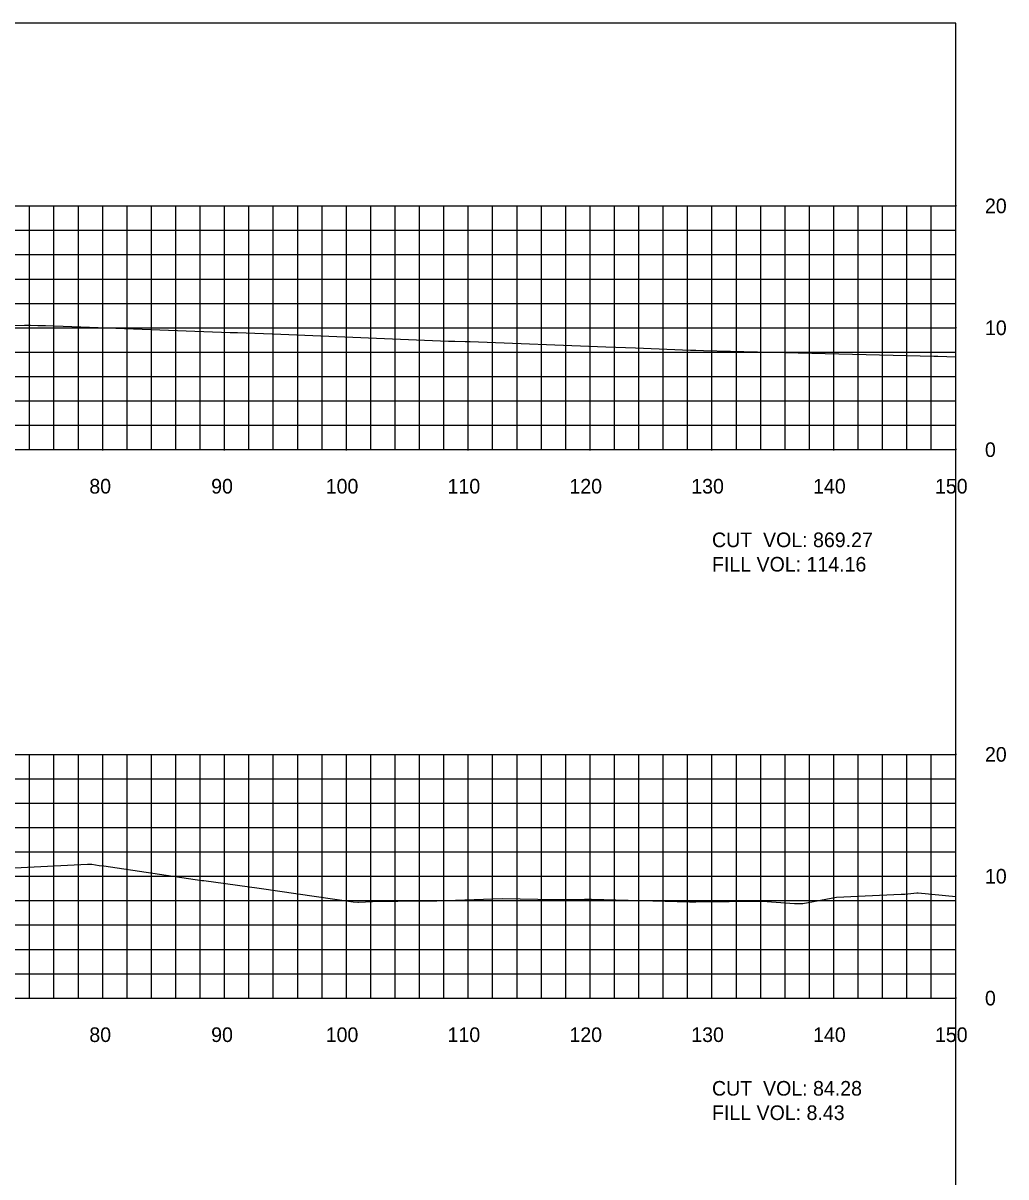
# Model space of a CAD drawing. Extents: x 1797419 to 1809236, y 248759 to 251512.
# Drawn here: x 1804404.5 to 1804485.1, y 250174.8 to 250269.4 of the extents above; entities that cross this region are included whole.
import ezdxf

# ---------------------------------------------------------------- set-up
doc = ezdxf.new("R2010")
doc.units = 0
for name, color, linetype in [('10', 7, 'Continuous'), ('31', 7, 'Continuous'), ('60', 7, 'Continuous'), ('ANNO-TXT', 7, 'Continuous'), ('Level 62', 7, 'Continuous'), ('M-ROADS', 7, 'Continuous')]:
    doc.layers.add(name, color=color, linetype=linetype)

msp = doc.modelspace()

# ---------------------------------------------------------------- linework, layer by layer
msp.add_lwpolyline([(1804181.002, 250079.432), (1804481.002, 250079.432), (1804481.002, 250269.432), (1804181.002, 250269.432)], close=True)
at = {"layer": '60'}
for p, q in [((1804481.002, 250234.432), (1804481.002, 250254.432)), ((1804481.062, 250254.432), (1804481.002, 250254.432)), ((1804481.062, 250244.432), (1804481.002, 250244.432)), ((1804181.002, 250234.432), (1804481.002, 250234.432)), ((1804411.002, 250234.372), (1804411.002, 250234.432)), ((1804421.002, 250234.372), (1804421.002, 250234.432)), ((1804431.002, 250234.372), (1804431.002, 250234.432)), ((1804441.002, 250234.372), (1804441.002, 250234.432)), ((1804451.002, 250234.372), (1804451.002, 250234.432)), ((1804461.002, 250234.372), (1804461.002, 250234.432)), ((1804471.002, 250234.372), (1804471.002, 250234.432)), ((1804481.002, 250234.372), (1804481.002, 250234.432)), ((1804481.062, 250234.432), (1804481.002, 250234.432)), ((1804481.002, 250189.432), (1804481.002, 250209.432)), ((1804481.062, 250209.432), (1804481.002, 250209.432)), ((1804481.062, 250199.432), (1804481.002, 250199.432)), ((1804181.002, 250189.432), (1804481.002, 250189.432)), ((1804411.002, 250189.372), (1804411.002, 250189.432)), ((1804421.002, 250189.372), (1804421.002, 250189.432)), ((1804431.002, 250189.372), (1804431.002, 250189.432)), ((1804441.002, 250189.372), (1804441.002, 250189.432)), ((1804451.002, 250189.372), (1804451.002, 250189.432)), ((1804461.002, 250189.372), (1804461.002, 250189.432)), ((1804471.002, 250189.372), (1804471.002, 250189.432)), ((1804481.002, 250189.372), (1804481.002, 250189.432)), ((1804481.062, 250189.432), (1804481.002, 250189.432))]:
    msp.add_line(p, q, dxfattribs=at)
at = {"layer": 'Level 62'}
for p, q in [((1804181.002, 250254.432), (1804481.002, 250254.432)), ((1804405.002, 250234.432), (1804405.002, 250254.432)), ((1804407.002, 250234.432), (1804407.002, 250254.432)), ((1804409.002, 250234.432), (1804409.002, 250254.432)), ((1804411.002, 250234.432), (1804411.002, 250254.432)), ((1804413.002, 250234.432), (1804413.002, 250254.432)), ((1804415.002, 250234.432), (1804415.002, 250254.432)), ((1804417.002, 250234.432), (1804417.002, 250254.432)), ((1804419.002, 250234.432), (1804419.002, 250254.432)), ((1804421.002, 250234.432), (1804421.002, 250254.432)), ((1804423.002, 250234.432), (1804423.002, 250254.432)), ((1804425.002, 250234.432), (1804425.002, 250254.432)), ((1804427.002, 250234.432), (1804427.002, 250254.432)), ((1804429.002, 250234.432), (1804429.002, 250254.432)), ((1804431.002, 250234.432), (1804431.002, 250254.432)), ((1804433.002, 250234.432), (1804433.002, 250254.432)), ((1804435.002, 250234.432), (1804435.002, 250254.432)), ((1804437.002, 250234.432), (1804437.002, 250254.432)), ((1804439.002, 250234.432), (1804439.002, 250254.432)), ((1804441.002, 250234.432), (1804441.002, 250254.432)), ((1804443.002, 250234.432), (1804443.002, 250254.432)), ((1804445.002, 250234.432), (1804445.002, 250254.432)), ((1804447.002, 250234.432), (1804447.002, 250254.432)), ((1804449.002, 250234.432), (1804449.002, 250254.432)), ((1804451.002, 250234.432), (1804451.002, 250254.432)), ((1804453.002, 250234.432), (1804453.002, 250254.432)), ((1804455.002, 250234.432), (1804455.002, 250254.432)), ((1804457.002, 250234.432), (1804457.002, 250254.432)), ((1804459.002, 250234.432), (1804459.002, 250254.432)), ((1804461.002, 250234.432), (1804461.002, 250254.432)), ((1804463.002, 250234.432), (1804463.002, 250254.432)), ((1804465.002, 250234.432), (1804465.002, 250254.432)), ((1804467.002, 250234.432), (1804467.002, 250254.432)), ((1804469.002, 250234.432), (1804469.002, 250254.432)), ((1804471.002, 250234.432), (1804471.002, 250254.432)), ((1804473.002, 250234.432), (1804473.002, 250254.432)), ((1804475.002, 250234.432), (1804475.002, 250254.432)), ((1804477.002, 250234.432), (1804477.002, 250254.432)), ((1804479.002, 250234.432), (1804479.002, 250254.432)), ((1804481.002, 250234.432), (1804481.002, 250254.432)), ((1804181.002, 250252.432), (1804481.002, 250252.432)), ((1804181.002, 250250.432), (1804481.002, 250250.432)), ((1804181.002, 250248.432), (1804481.002, 250248.432)), ((1804181.002, 250246.432), (1804481.002, 250246.432)), ((1804181.002, 250244.432), (1804481.002, 250244.432)), ((1804181.002, 250242.432), (1804481.002, 250242.432)), ((1804181.002, 250240.432), (1804481.002, 250240.432)), ((1804181.002, 250238.432), (1804481.002, 250238.432)), ((1804181.002, 250236.432), (1804481.002, 250236.432)), ((1804181.002, 250234.432), (1804481.002, 250234.432)), ((1804181.002, 250209.432), (1804481.002, 250209.432)), ((1804405.002, 250189.432), (1804405.002, 250209.432)), ((1804407.002, 250189.432), (1804407.002, 250209.432)), ((1804409.002, 250189.432), (1804409.002, 250209.432)), ((1804411.002, 250189.432), (1804411.002, 250209.432)), ((1804413.002, 250189.432), (1804413.002, 250209.432)), ((1804415.002, 250189.432), (1804415.002, 250209.432)), ((1804417.002, 250189.432), (1804417.002, 250209.432)), ((1804419.002, 250189.432), (1804419.002, 250209.432)), ((1804421.002, 250189.432), (1804421.002, 250209.432)), ((1804423.002, 250189.432), (1804423.002, 250209.432)), ((1804425.002, 250189.432), (1804425.002, 250209.432)), ((1804427.002, 250189.432), (1804427.002, 250209.432)), ((1804429.002, 250189.432), (1804429.002, 250209.432)), ((1804431.002, 250189.432), (1804431.002, 250209.432)), ((1804433.002, 250189.432), (1804433.002, 250209.432)), ((1804435.002, 250189.432), (1804435.002, 250209.432)), ((1804437.002, 250189.432), (1804437.002, 250209.432)), ((1804439.002, 250189.432), (1804439.002, 250209.432)), ((1804441.002, 250189.432), (1804441.002, 250209.432)), ((1804443.002, 250189.432), (1804443.002, 250209.432)), ((1804445.002, 250189.432), (1804445.002, 250209.432)), ((1804447.002, 250189.432), (1804447.002, 250209.432)), ((1804449.002, 250189.432), (1804449.002, 250209.432)), ((1804451.002, 250189.432), (1804451.002, 250209.432)), ((1804453.002, 250189.432), (1804453.002, 250209.432)), ((1804455.002, 250189.432), (1804455.002, 250209.432)), ((1804457.002, 250189.432), (1804457.002, 250209.432)), ((1804459.002, 250189.432), (1804459.002, 250209.432)), ((1804461.002, 250189.432), (1804461.002, 250209.432)), ((1804463.002, 250189.432), (1804463.002, 250209.432)), ((1804465.002, 250189.432), (1804465.002, 250209.432)), ((1804467.002, 250189.432), (1804467.002, 250209.432)), ((1804469.002, 250189.432), (1804469.002, 250209.432)), ((1804471.002, 250189.432), (1804471.002, 250209.432)), ((1804473.002, 250189.432), (1804473.002, 250209.432)), ((1804475.002, 250189.432), (1804475.002, 250209.432)), ((1804477.002, 250189.432), (1804477.002, 250209.432)), ((1804479.002, 250189.432), (1804479.002, 250209.432)), ((1804481.002, 250189.432), (1804481.002, 250209.432)), ((1804181.002, 250207.432), (1804481.002, 250207.432)), ((1804181.002, 250205.432), (1804481.002, 250205.432)), ((1804181.002, 250203.432), (1804481.002, 250203.432)), ((1804181.002, 250201.432), (1804481.002, 250201.432)), ((1804181.002, 250199.432), (1804481.002, 250199.432)), ((1804181.002, 250197.432), (1804481.002, 250197.432)), ((1804181.002, 250195.432), (1804481.002, 250195.432)), ((1804181.002, 250193.432), (1804481.002, 250193.432)), ((1804181.002, 250191.432), (1804481.002, 250191.432)), ((1804181.002, 250189.432), (1804481.002, 250189.432))]:
    msp.add_line(p, q, dxfattribs=at)
at = {"layer": 'M-ROADS'}
for points in [[(1804399.708, 250244.594), (1804404.591, 250244.644), (1804405.052, 250244.643), (1804405.071, 250244.643), (1804405.666, 250244.63), (1804405.697, 250244.63), (1804406.308, 250244.621), (1804421.466, 250244.049), (1804421.968, 250244.039), (1804422.052, 250244.038), (1804424.905, 250243.928), (1804425.015, 250243.926), (1804425.613, 250243.916), (1804439.371, 250243.336), (1804439.838, 250243.327), (1804439.894, 250243.326), (1804440.743, 250243.301), (1804441.151, 250243.303), (1804452.3, 250242.859), (1804454.721, 250242.778), (1804459.248, 250242.602), (1804459.647, 250242.591), (1804459.677, 250242.59), (1804460.292, 250242.577), (1804464.739, 250242.465), (1804479.198, 250242.099), (1804479.523, 250242.093), (1804481.002, 250242.061)], [(1804401.692, 250200.004), (1804404.814, 250200.166), (1804409.74, 250200.426), (1804409.801, 250200.424), (1804410.112, 250200.43), (1804410.697, 250200.326), (1804411.085, 250200.299), (1804419.129, 250199.09), (1804419.31, 250199.085), (1804423.835, 250198.462), (1804431.548, 250197.319), (1804431.926, 250197.315), (1804432.005, 250197.314), (1804433.137, 250197.362), (1804437.328, 250197.407), (1804438.04, 250197.42), (1804438.431, 250197.428), (1804443.787, 250197.613), (1804448.191, 250197.53), (1804450.526, 250197.557), (1804450.757, 250197.554), (1804451.112, 250197.549), (1804459.142, 250197.34), (1804459.439, 250197.339), (1804459.674, 250197.338), (1804465.148, 250197.378), (1804467.771, 250197.208), (1804468.141, 250197.205), (1804468.462, 250197.202), (1804471.224, 250197.721), (1804476.532, 250197.954), (1804476.829, 250197.957), (1804477.824, 250198.082), (1804477.93, 250198.084), (1804481.002, 250197.761)]]:
    msp.add_lwpolyline(points, dxfattribs=at)

# ---------------------------------------------------------------- texts
at = {"layer": '10'}
for s, p in [('80', (1804409.901, 250230.832)), ('90', (1804419.901, 250230.832)), ('100', (1804429.301, 250230.832)), ('110', (1804439.301, 250230.832)), ('120', (1804449.301, 250230.832)), ('130', (1804459.301, 250230.832)), ('140', (1804469.301, 250230.832)), ('150', (1804479.301, 250230.832)), ('80', (1804409.901, 250185.832)), ('90', (1804419.901, 250185.832)), ('100', (1804429.301, 250185.832)), ('110', (1804439.301, 250185.832)), ('120', (1804449.301, 250185.832)), ('130', (1804459.301, 250185.832)), ('140', (1804469.301, 250185.832)), ('150', (1804479.301, 250185.832))]:
    msp.add_text(s, height=1.2, dxfattribs=at).set_placement(p)
at = {"layer": '31'}
for s, p in [('20', (1804483.402, 250253.832)), ('10', (1804483.402, 250243.832)), ('0', (1804483.402, 250233.832)), ('20', (1804483.402, 250208.832)), ('10', (1804483.402, 250198.832)), ('0', (1804483.402, 250188.832))]:
    msp.add_text(s, height=1.2, dxfattribs=at).set_placement(p)
at = {"layer": 'ANNO-TXT'}
for s, p in [('CUT  VOL: 869.27', (1804461.002, 250226.432)), ('FILL VOL: 114.16', (1804461.002, 250224.432)), ('CUT  VOL: 84.28', (1804461.002, 250181.432)), ('FILL VOL: 8.43', (1804461.002, 250179.432))]:
    msp.add_text(s, height=1.2, dxfattribs=at).set_placement(p)

doc.saveas('drawing.dxf')
